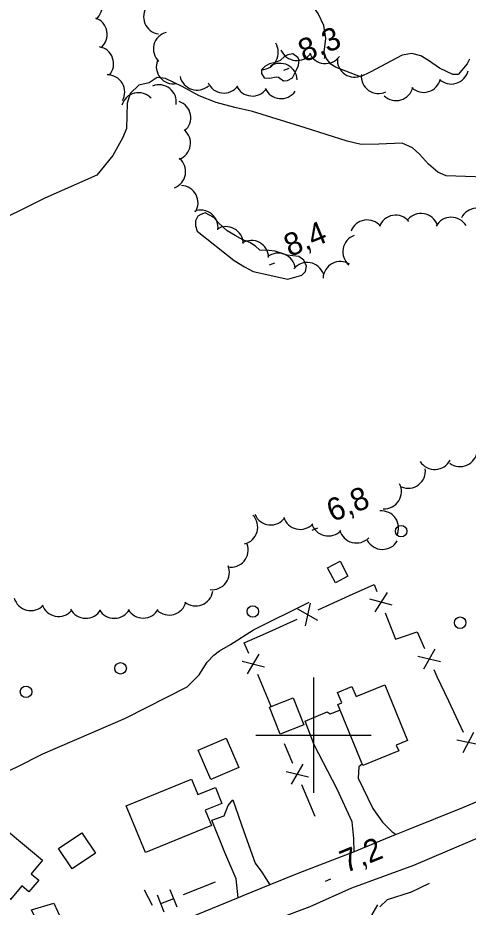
# Model space of a CAD drawing. Extents: x 362852 to 366875, y 5563573 to 5566479.
# Drawn here: x 363948.7 to 364026.8, y 5565170.1 to 5565324.6 of the extents above; entities that cross this region are included whole.
import ezdxf

# ---------------------------------------------------------------- set-up
doc = ezdxf.new("R2010")
doc.units = 0
for name, color, linetype in [('Niveau 19', 7, 'Continuous'), ('Niveau 2', 7, 'Continuous'), ('Niveau 21', 7, 'Continuous'), ('Niveau 22', 7, 'Continuous'), ('Niveau 3', 7, 'Continuous'), ('Niveau 31', 7, 'Continuous'), ('Niveau 36', 7, 'Continuous'), ('Niveau 37', 7, 'Continuous'), ('Niveau 44', 7, 'Continuous'), ('Niveau 61', 7, 'Continuous')]:
    doc.layers.add(name, color=color, linetype=linetype)

msp = doc.modelspace()

# ---------------------------------------------------------------- linework, layer by layer
at = {"layer": 'Niveau 19'}
for points in [[(364007.04, 5565179.73), (364007.02, 5565182.09), (364006.72, 5565184.96), (364004.1, 5565190.62), (364000.12, 5565198.34), (363998.57, 5565202.46), (364002.35, 5565204.05), (364002.92, 5565203.72), (364004.6, 5565204.35)], [(364008.45, 5565194.96), (364007.89, 5565194.48), (364007.78, 5565192.53), (364010.3, 5565187.27), (364011.95, 5565184.9), (364013.65, 5565183.25), (364014.36, 5565182.76)], [(363986.96, 5565171.77), (363986.6, 5565175.09), (363984.63, 5565179.65), (363982.34, 5565185.27), (363984.5, 5565186.01), (363985.17, 5565187.82), (363986, 5565188.77), (363987.9, 5565183.26), (363989.9, 5565177.8), (363991.05, 5565176.2), (363992.44, 5565174)], [(363952.68, 5565158.37), (363953.27, 5565160.13), (363953.49, 5565162.43), (363953.05, 5565165.68), (363951.08, 5565169.7), (363954.97, 5565170.86), (363956.21, 5565168.03), (363957.91, 5565165.1), (363958.65, 5565163.41), (363960.18, 5565161.01)]]:
    msp.add_lwpolyline(points, dxfattribs=at)
at = {"layer": 'Niveau 2'}
for points in [[(364001.83, 5565318.59), (364002.17, 5565320.98), (364001.77, 5565323.2), (364000.79, 5565325.31), (363999.29, 5565327.45), (363997.69, 5565329.55), (363996.44, 5565331.42), (363994.94, 5565333.56), (363993.39, 5565335.55), (363991.57, 5565338.19), (363990.26, 5565341.41), (363988.79, 5565345.33), (363987.3, 5565348.1), (363980.33, 5565357.27), (363977.03, 5565360.18), (363974.2, 5565361.91), (363971.05, 5565364.75), (363969.11, 5565366.46), (363957.35, 5565380.07), (363954.13, 5565383.39), (363951.01, 5565386.76), (363948.8, 5565389.74), (363946.02, 5565394.74)], [(363997.01, 5565315.42), (363997.41, 5565316.27), (363997.51, 5565317.25), (363997.28, 5565317.66), (363996.4, 5565318.3), (363995.53, 5565318.13), (363994.96, 5565317.84), (363994.24, 5565317.16), (363993.33, 5565316.79), (363992.36, 5565316.58), (363991.54, 5565316.12), (363990.98, 5565315.51), (363990.98, 5565314.89), (363991.47, 5565314.15), (363992.45, 5565314.05), (363993.53, 5565314.3), (363993.94, 5565314.22), (363994.8, 5565313.63), (363995.47, 5565313.66), (363996.34, 5565314.14), (363997.01, 5565315.42)], [(364008.13, 5565314.28), (364003.83, 5565315.96), (364002.99, 5565316.5), (364002.19, 5565317.55), (364001.83, 5565318.59)], [(364025.1, 5565314.73), (364024.16, 5565314.73), (364021.86, 5565315.79), (364019.94, 5565317.13), (364018.61, 5565317.96), (364017.09, 5565318.34), (364015.38, 5565318.08), (364009.85, 5565315.11), (364008.13, 5565314.28)], [(364027.08, 5565317.37), (364026.66, 5565316.57), (364025.1, 5565314.73)], [(363995.44, 5565283.33), (363993.35, 5565284.03), (363992.24, 5565284.14), (363990.67, 5565284.19), (363989.95, 5565284.89), (363988.93, 5565285.54), (363987.75, 5565286), (363986.44, 5565286.77), (363985.05, 5565287.58), (363983.57, 5565288.92), (363982.69, 5565289.87), (363981.22, 5565290.71), (363980.48, 5565290.4), (363979.91, 5565290.11), (363979.54, 5565289.33), (363979.53, 5565288.44), (363979.84, 5565287.51)], [(363979.84, 5565287.51), (363986.21, 5565282.42), (363988.04, 5565281.29), (363989.54, 5565280.53), (363995.57, 5565279.18), (363997.98, 5565279.86), (363998.59, 5565280.49), (363998.77, 5565281.44), (363998.35, 5565282.46), (363997.47, 5565283.1), (363996.42, 5565283.23), (363995.44, 5565283.33)]]:
    msp.add_lwpolyline(points, dxfattribs=at)
at = {"layer": 'Niveau 21'}
for points in [[(363993.59, 5565168.04), (363999.45, 5565170.26), (364006.68, 5565173.48), (364017.42, 5565177.45), (364030.33, 5565182.91), (364041.49, 5565187.59), (364044.23, 5565188.68), (364053.71, 5565192.45), (364061.43, 5565195.61), (364062.75, 5565196.16), (364069.76, 5565198.82), (364076.7, 5565200.7), (364081.21, 5565201.11), (364083.69, 5565200.69), (364085.71, 5565200.33), (364090.12, 5565198.59), (364093.98, 5565196.3), (364101.62, 5565190.79), (364109.33, 5565184.24), (364117.4, 5565176.73), (364126.01, 5565168.87)], [(364053.96, 5565198.92), (364053.9, 5565198.89), (364048.94, 5565197), (364039.24, 5565192.98), (364025.88, 5565187.4), (364016.09, 5565183.48), (364014.36, 5565182.76), (364013.91, 5565182.57), (364007.04, 5565179.73), (363997.28, 5565175.97), (363992.44, 5565174), (363987.73, 5565172.09), (363986.96, 5565171.77), (363976.62, 5565167.53)]]:
    msp.add_lwpolyline(points, dxfattribs=at)
at = {"layer": 'Niveau 22'}
for points in [[(364034.75, 5565296.7), (364023.02, 5565297.13), (364021.59, 5565297.73), (364019.96, 5565299.13), (364018.38, 5565300.86), (364017.17, 5565302), (364015.37, 5565302.76), (364011.35, 5565302.6), (364008.25, 5565302.53), (364005.85, 5565303.16), (363998.54, 5565305.44), (363989.4, 5565308.31), (363986.38, 5565308.99), (363983.1, 5565309.87), (363980.15, 5565311.02), (363977.21, 5565312.65), (363974.33, 5565314), (363972.87, 5565314.21), (363971.47, 5565313.24), (363969.7, 5565312.83), (363968.17, 5565311.39), (363967.65, 5565309.73), (363967.58, 5565305.31), (363966.94, 5565303.79), (363965.19, 5565300.67), (363962.41, 5565297.21), (363953.4, 5565293.26), (363942.96, 5565288.07)], [(363928.33, 5565188.22), (363933.3, 5565189.42), (363942.28, 5565191.78), (363945.87, 5565193.29), (363947.71, 5565194.1), (363948.6, 5565194.52), (363953.03, 5565196.76), (363967.36, 5565202.95), (363978.06, 5565208.41), (363978.81, 5565209.16), (363980.16, 5565210.46), (363981.57, 5565212.67), (363982.7, 5565213.88), (363983.69, 5565214.67), (363985.61, 5565215.77), (363989.59, 5565218.28), (363999.23, 5565223.09)]]:
    msp.add_lwpolyline(points, dxfattribs=at)
at = {"layer": 'Niveau 3'}
for p, q in [((363994.85, 5565315.44), (363995.81, 5565315.83)), ((363992.36, 5565281.64), (363993.32, 5565282.03)), ((363999.78, 5565235.61), (364000.74, 5565236)), ((364002.08, 5565174.67), (364003.04, 5565175.06))]:
    msp.add_line(p, q, dxfattribs=at)
at = {"layer": 'Niveau 31'}
for points in [[(364004.61, 5565230.19), (364005.98, 5565227.62), (364003.8, 5565226.46), (364002.43, 5565229.03), (364004.61, 5565230.19)], [(364012.37, 5565208.72), (364016.32, 5565199.08), (364014.37, 5565198.28), (364014.79, 5565197.27), (364008.56, 5565194.71), (364004.2, 5565205.33), (364004.93, 5565205.63), (364004.19, 5565207.44), (364006.67, 5565208.46), (364007.4, 5565206.69), (364012.37, 5565208.72)], [(363996.48, 5565206.5), (363998.34, 5565201.78), (363994.21, 5565200.15), (363992.35, 5565204.88), (363996.48, 5565206.5)], [(363984.87, 5565199.48), (363987.07, 5565194.39), (363982.2, 5565192.3), (363980, 5565197.38), (363984.87, 5565199.48)], [(363982.31, 5565184.34), (363970.84, 5565179.64), (363967.52, 5565187.72), (363978.86, 5565192.37), (363979.96, 5565189.69), (363982.97, 5565190.92), (363984.1, 5565188.15), (363981.23, 5565186.97), (363982.31, 5565184.34)], [(363949.4, 5565173.83), (363947.42, 5565171.46), (363937.86, 5565179.42), (363943.5, 5565186.2), (363952.99, 5565178.3), (363951.02, 5565175.94), (363952.33, 5565174.85), (363950.63, 5565172.81), (363949.4, 5565173.83)], [(363962.16, 5565179.49), (363958.1, 5565176.8), (363955.76, 5565180.33), (363959.82, 5565183.02), (363962.16, 5565179.49)]]:
    msp.add_lwpolyline(points, dxfattribs=at)
at = {"layer": 'Niveau 36'}
for centre in [(364015.22, 5565235.43), (363989.48, 5565221.48), (364025.46, 5565219.53), (363966.53, 5565211.61), (363950.13, 5565207.52)]:
    msp.add_circle(centre, 1, dxfattribs=at)
at = {"layer": 'Niveau 37'}
for p, q in [((364000.8, 5565221.79), (364006.27, 5565224.26)), ((364012.79, 5565224.79), (364010.67, 5565221.39)), ((363999.41, 5565222.91), (363998.54, 5565219.01)), ((364013.66, 5565222.55), (364009.8, 5565223.62)), ((363997.22, 5565221.92), (364000.72, 5565219.99)), ((363991.68, 5565217.67), (363997.15, 5565220.14)), ((364021.06, 5565214.96), (364019.1, 5565211.48)), ((363987.61, 5565212.84), (363991.49, 5565211.88)), ((363988.55, 5565210.63), (363990.56, 5565214.09)), ((364022.03, 5565212.76), (364018.13, 5565213.67)), ((363992.67, 5565205), (363990.33, 5565210.52)), ((364023.42, 5565205.94), (364025.98, 5565200.52)), ((364027.77, 5565200.48), (364025.9, 5565196.94)), ((364028.79, 5565198.31), (364024.87, 5565199.11)), ((363996.41, 5565195.09), (363994.97, 5565198.48)), ((363996.19, 5565191.51), (363998.2, 5565194.97)), ((363995.25, 5565193.72), (363999.13, 5565192.76)), ((364000.31, 5565185.88), (363997.97, 5565191.4)), ((363980.2, 5565173.44), (363982.99, 5565174.56)), ((363970.63, 5565173.16), (363972, 5565170.49)), ((363977.42, 5565172.33), (363980.2, 5565173.44)), ((364009.15, 5565167.08), (364011.17, 5565170.53))]:
    msp.add_line(p, q, dxfattribs=at)
for points in [[(364006.27, 5565224.26), (364010.53, 5565226.18), (364011.01, 5565224.95)], [(364012.46, 5565221.22), (364014.23, 5565216.68), (364015.3, 5565217.03)], [(363988.77, 5565214.21), (363988, 5565216.01), (363991.68, 5565217.67)], [(364015.3, 5565217.03), (364018.02, 5565217.92), (364019.28, 5565215.05)], [(364020.89, 5565211.38), (364021.42, 5565210.18), (364023.42, 5565205.94)], [(364016.83, 5565172.72), (364016.87, 5565172.73), (364020.15, 5565174.33)], [(363976.34, 5565170.17), (363975.15, 5565173.14)], [(364011.53, 5565170.21), (364012.86, 5565171.49), (364016.83, 5565172.72)], [(363974.11, 5565169.28), (363972.92, 5565172.25)], [(363973.52, 5565170.76), (363975.75, 5565171.66)]]:
    msp.add_lwpolyline(points, dxfattribs=at)
at = {"layer": 'Niveau 44'}
for centre, start, end in [((363960.35, 5565326.61), 309.7994, 69.7773), ((363973.53, 5565324.72), 142.1165, 262.0944), ((363961.2, 5565321.68), 309.7994, 69.7773), ((363975.22, 5565319.13), 105.4471, 225.4251), ((363962.32, 5565316.56), 319.7175, 79.6955), ((363990.9, 5565318.55), 271.7442, 31.7221), ((363997.1, 5565320.14), 203.9301, 323.908), ((364002.07, 5565319.61), 203.9301, 323.908), ((363975.72, 5565316.08), 159.5727, 279.5506), ((363994.17, 5565313.65), 2.7808, 122.7588), ((364007.14, 5565317.25), 175.9883, 295.9663), ((364023.9, 5565316.05), 226.6576, 346.6355), ((363964.25, 5565311.65), 330.551, 90.529), ((363979.78, 5565314.99), 191.8758, 311.8537), ((363984.45, 5565314.48), 203.5015, 323.4795), ((364011.3, 5565314.4), 174.5936, 294.5715), ((364019.11, 5565314.61), 226.6576, 346.6355), ((363973.2, 5565309.92), 351.8819, 111.8599), ((363989.38, 5565313.97), 204.9007, 324.8787), ((363994.36, 5565313.52), 204.9007, 324.8787), ((364014.32, 5565313.18), 226.6576, 346.6355), ((363969.63, 5565308.55), 43.4524, 163.4303), ((363975.7, 5565307.2), 310.6129, 70.5908), ((363975.66, 5565302.8), 290.376, 50.354), ((363974.82, 5565297.87), 290.376, 50.354), ((363976.97, 5565292.44), 327.735, 87.713), ((363980.44, 5565288.16), 351.7261, 111.704), ((364014.25, 5565287.28), 39.4837, 159.4616), ((364018.67, 5565287.58), 19.9503, 139.9282), ((364028.36, 5565288.49), 33.6298, 153.6078), ((364009.32, 5565286.46), 39.4837, 159.4616), ((364023.9, 5565286.93), 30.8254, 150.8034), ((363984.82, 5565285.3), 1.3081, 121.286), ((363989.21, 5565282.89), 1.3081, 121.286), ((364008.08, 5565283.94), 109.9624, 229.9403), ((363993.86, 5565280.7), 7.315, 127.2929), ((363998.92, 5565279.06), 20.4722, 140.4502), ((364004.66, 5565279.24), 57.5223, 177.5002), ((364025.42, 5565249.63), 233.6447, 353.6227), ((364021.05, 5565249.14), 212.817, 332.7949), ((364016.43, 5565245.87), 246.9511, 6.9291), ((364012.27, 5565242.31), 266.9655, 26.9435), ((363987.33, 5565236.12), 283.7126, 43.6906), ((363992.59, 5565239.51), 203.7284, 323.7064), ((363997.7, 5565238.73), 196.8552, 316.8331), ((364011.77, 5565235.95), 334.5665, 94.5445), ((364002.57, 5565237.59), 196.8552, 316.8331), ((364007.46, 5565236.37), 195.3111, 315.289), ((363985.67, 5565232.16), 260.0077, 19.9856), ((364011.96, 5565235.26), 209.0448, 329.0227), ((363982.42, 5565228.26), 262.9622, 22.9402), ((363950.95, 5565224.64), 196.0727, 316.0506), ((363979.55, 5565225.43), 231.3813, 351.3592), ((363955.78, 5565223.62), 198.6658, 318.6437), ((363974.96, 5565223.85), 226.0793, 346.0573), ((363960.5, 5565223.3), 208.3659, 328.3438), ((363965.44, 5565223.29), 210.4659, 330.4438), ((363970.44, 5565223.33), 210.4659, 330.4438)]:
    msp.add_arc(centre, 3, start, end, dxfattribs=at)
at = {"layer": 'Niveau 61'}
for p, q in [((364000, 5565210), (364000, 5565190)), ((363990, 5565200), (364010, 5565200))]:
    msp.add_line(p, q, dxfattribs=at)

# ---------------------------------------------------------------- texts
at = {"layer": 'Niveau 3'}
for s, p in [('8,3  ', (363998.36, 5565316.8)), ('8,4  ', (363995.87, 5565283)), ('6,8  ', (364003.29, 5565236.97)), ('7,2  ', (364005.59, 5565176.03))]:
    msp.add_text(s, height=3.93, rotation=22.09, dxfattribs=at).set_placement(p)

doc.saveas('drawing.dxf')
